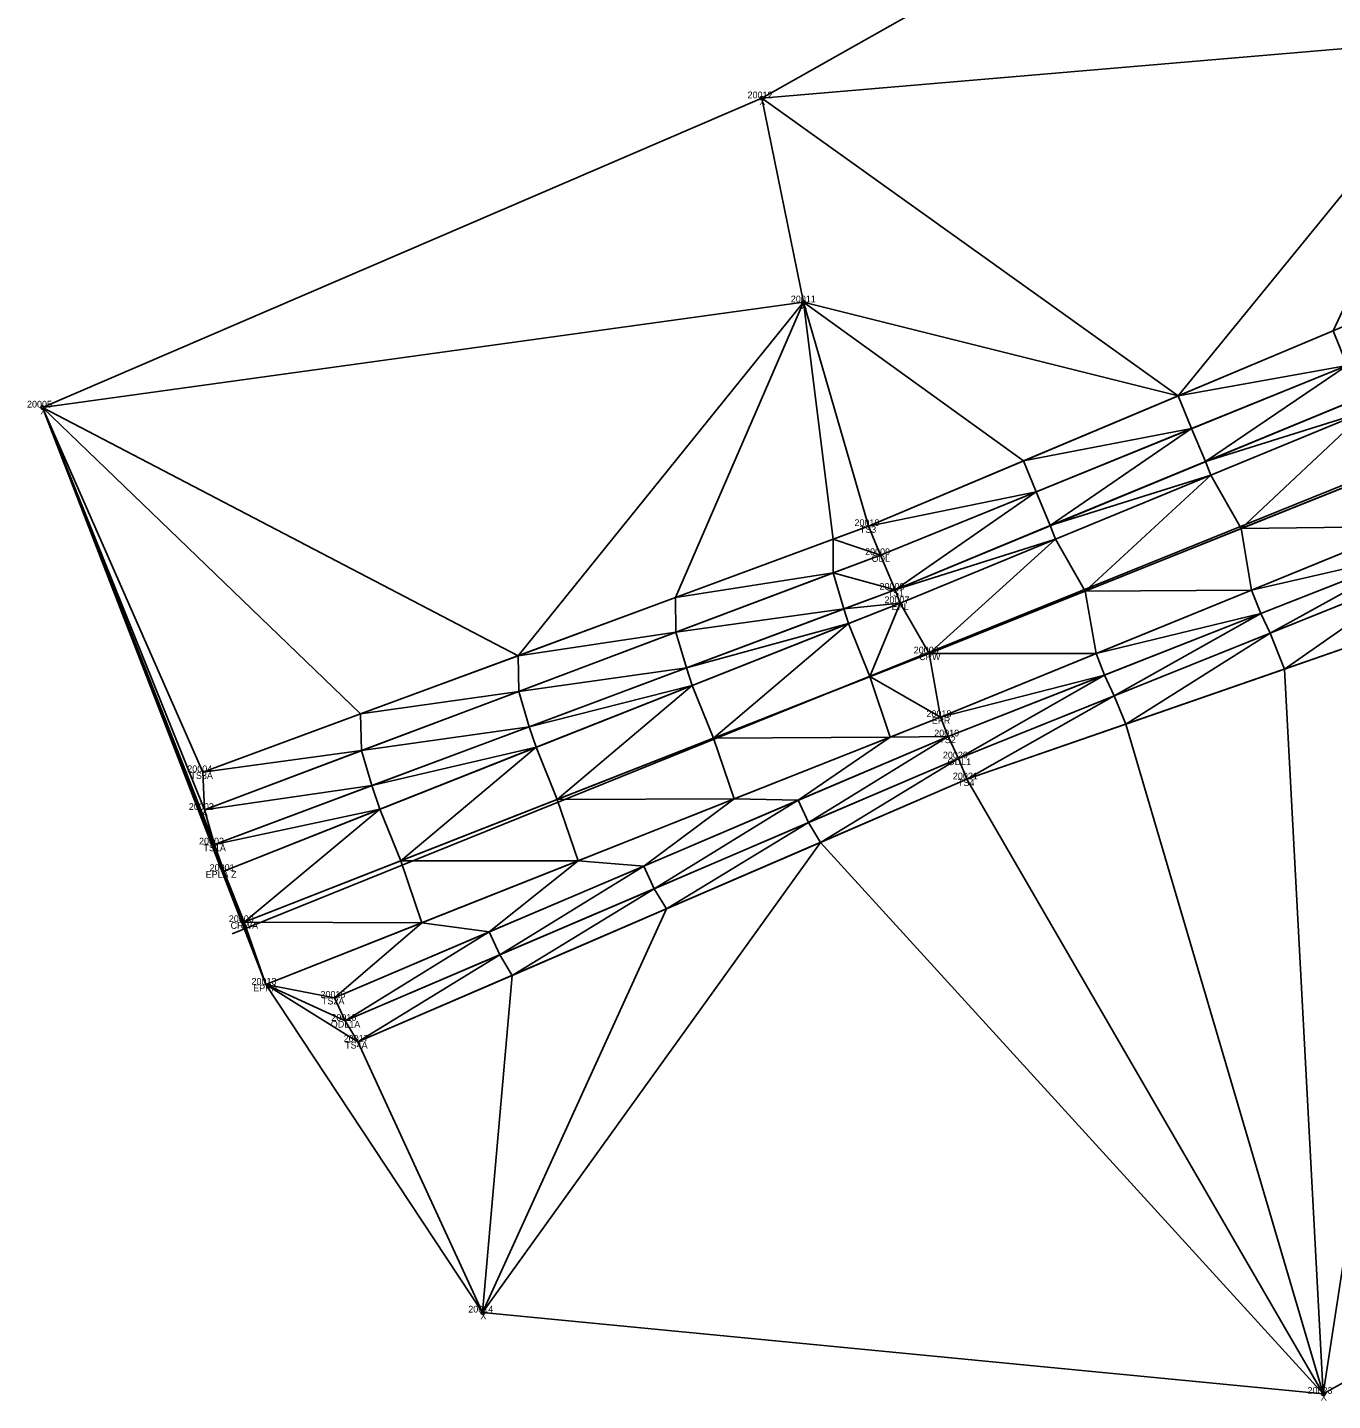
# Model space of a CAD drawing. Extents: x 1966740 to 1969291, y 1117379 to 1118460.
# Drawn here: x 1966740.3 to 1966934.5, y 1117378.7 to 1117583 of the extents above; entities that cross this region are included whole.
import ezdxf

# ---------------------------------------------------------------- set-up
doc = ezdxf.new("R2010")
doc.units = 0
for name, color, linetype in [('Level 1', 7, 'Continuous'), ('Level 3', 7, 'Continuous'), ('Level 30', 7, 'Continuous'), ('Level 35', 7, 'Continuous'), ('Level 50', 7, 'Continuous'), ('Level 52', 7, 'Continuous'), ('Level 53', 7, 'Continuous'), ('Level 56', 7, 'Continuous'), ('Level 6', 7, 'Continuous'), ('Level 62', 7, 'Continuous')]:
    doc.layers.add(name, color=color, linetype=linetype)

msp = doc.modelspace()

# ---------------------------------------------------------------- linework, layer by layer
at = {"layer": 'Level 1'}
msp.add_line((1966770.74, 1117448.12), (1967849.47, 1117883.86), dxfattribs=at)
at = {"layer": 'Level 3'}
for points in [[(1966768.15, 1117461.43), (1966869.41, 1117499.34), (1967070.52, 1117582.35), (1967171.25, 1117624.02), (1967269.74, 1117664.9), (1967320.21, 1117685.71), (1967369.37, 1117708.48), (1967468.51, 1117746.66), (1967564.6, 1117784.47), (1967654.68, 1117828.05), (1967680.1, 1117841.48), (1967687.91, 1117842.93), (1967691.45, 1117838.71), (1967693.03, 1117834.22)], [(1966769.51, 1117457.48), (1966870.16, 1117497.34), (1966971.19, 1117538.95), (1967071.09, 1117580.24), (1967172.6, 1117621.53), (1967270.79, 1117661.66), (1967321.12, 1117682.57), (1967371.52, 1117702.88), (1967470.26, 1117741.55), (1967566.67, 1117779.5), (1967661.25, 1117817.53), (1967694.4, 1117831.19), (1967697.89, 1117822.8)], [(1966772.57, 1117449.88), (1966874.49, 1117489.87), (1966974.64, 1117529.93), (1967075.06, 1117571.68), (1967175.91, 1117613.34), (1967274.11, 1117653.69), (1967325.25, 1117674.8), (1967374.73, 1117695.01), (1967473.9, 1117733.1), (1967569.8, 1117771.9), (1967665.19, 1117809.79), (1967697.89, 1117822.8)], [(1966766.42, 1117472.19), (1966865.47, 1117508.82), (1967066.64, 1117593.45), (1967166.55, 1117636.11), (1967264.62, 1117677.56), (1967315.66, 1117698.57), (1967367.9, 1117716.34), (1967464.92, 1117753.87), (1967560.73, 1117793.63)], [(1966775.75, 1117440.57), (1966876.18, 1117480.39), (1966978.46, 1117522.15), (1967078.26, 1117563.06), (1967180.7, 1117605.06), (1967277.98, 1117644.72), (1967308.82, 1117656.67)], [(1966786.01, 1117438.62), (1966877.32, 1117477.51), (1966981.49, 1117518.47), (1967035.72, 1117540.87), (1967038.77, 1117541.05)], [(1966789.47, 1117432.06), (1966880.12, 1117471.13), (1966985.94, 1117507.88), (1967038.45, 1117537.97), (1967038.77, 1117541.05)]]:
    msp.add_lwpolyline(points, dxfattribs=at)
at = {"layer": 'Level 30'}
for centre in [(1966849.57, 1117572.49), (1966855.79, 1117542.12), (1966742.55, 1117526.46), (1966808.03, 1117391.77), (1966933.11, 1117379.67)]:
    msp.add_circle(centre, 0.25, dxfattribs=at)
at = {"layer": 'Level 35'}
for points in [[(1966849.57, 1117572.49), (1966942.02, 1117624.67), (1966955, 1117581.5)], [(1966849.57, 1117572.49), (1966955, 1117581.5), (1966911.55, 1117528.2)], [(1966911.55, 1117528.2), (1966955, 1117581.5), (1966934.59, 1117537.89)], [(1966742.55, 1117526.46), (1966849.57, 1117572.49), (1966855.79, 1117542.12)], [(1966849.57, 1117572.49), (1966911.55, 1117528.2), (1966855.79, 1117542.12)], [(1966742.55, 1117526.46), (1966855.79, 1117542.12), (1966813.31, 1117489.53)], [(1966813.31, 1117489.53), (1966855.79, 1117542.12), (1966836.76, 1117498.2)], [(1966836.76, 1117498.2), (1966855.79, 1117542.12), (1966860.21, 1117506.87)], [(1966855.79, 1117542.12), (1966911.55, 1117528.2), (1966888.51, 1117518.51)], [(1966855.79, 1117542.12), (1966888.51, 1117518.51), (1966865.47, 1117508.82)], [(1966855.79, 1117542.12), (1966865.47, 1117508.82), (1966860.21, 1117506.87)], [(1966911.55, 1117528.2), (1966934.59, 1117537.89), (1966936.7, 1117532.74)], [(1966911.55, 1117528.2), (1966936.7, 1117532.74), (1966913.55, 1117523.32)], [(1966913.55, 1117523.32), (1966936.7, 1117532.74), (1966915.62, 1117518.41)], [(1966915.62, 1117518.41), (1966936.7, 1117532.74), (1966938.72, 1117527.95)], [(1966742.55, 1117526.46), (1966766.42, 1117472.19), (1966766.64, 1117466.58)], [(1966742.55, 1117526.46), (1966766.64, 1117466.58), (1966768.15, 1117461.43)], [(1966742.55, 1117526.46), (1966768.15, 1117461.43), (1966769.51, 1117457.48)], [(1966742.55, 1117526.46), (1966769.51, 1117457.48), (1966775.75, 1117440.57)], [(1966742.55, 1117526.46), (1966813.31, 1117489.53), (1966789.87, 1117480.86)], [(1966742.55, 1117526.46), (1966789.87, 1117480.86), (1966766.42, 1117472.19)], [(1966888.51, 1117518.51), (1966911.55, 1117528.2), (1966913.55, 1117523.32)], [(1966915.62, 1117518.41), (1966938.72, 1117527.95), (1966939.5, 1117525.9)], [(1966915.62, 1117518.41), (1966939.5, 1117525.9), (1966916.39, 1117516.38)], [(1966916.39, 1117516.38), (1966939.5, 1117525.9), (1966920.9, 1117508.44)], [(1966920.9, 1117508.44), (1966939.5, 1117525.9), (1966944.11, 1117517.72)], [(1966888.51, 1117518.51), (1966913.55, 1117523.32), (1966890.4, 1117513.91)], [(1966890.4, 1117513.91), (1966913.55, 1117523.32), (1966892.51, 1117508.88)], [(1966892.51, 1117508.88), (1966913.55, 1117523.32), (1966915.62, 1117518.41)], [(1966865.47, 1117508.82), (1966888.51, 1117518.51), (1966890.4, 1117513.91)], [(1966892.51, 1117508.88), (1966915.62, 1117518.41), (1966916.39, 1117516.38)], [(1966892.51, 1117508.88), (1966916.39, 1117516.38), (1966893.27, 1117506.86)], [(1966893.27, 1117506.86), (1966916.39, 1117516.38), (1966897.69, 1117499.15)], [(1966897.69, 1117499.15), (1966916.39, 1117516.38), (1966920.9, 1117508.44)], [(1966920.9, 1117508.44), (1966944.11, 1117517.72), (1966945.61, 1117508.74)], [(1966865.47, 1117508.82), (1966890.4, 1117513.91), (1966867.24, 1117504.5)], [(1966867.24, 1117504.5), (1966890.4, 1117513.91), (1966869.41, 1117499.34)], [(1966869.41, 1117499.34), (1966890.4, 1117513.91), (1966892.51, 1117508.88)], [(1966860.21, 1117506.87), (1966865.47, 1117508.82), (1966867.24, 1117504.5)], [(1966869.41, 1117499.34), (1966892.51, 1117508.88), (1966893.27, 1117506.86)], [(1966897.69, 1117499.15), (1966920.9, 1117508.44), (1966922.47, 1117499.29)], [(1966920.9, 1117508.44), (1966945.61, 1117508.74), (1966922.47, 1117499.29)], [(1966922.47, 1117499.29), (1966945.61, 1117508.74), (1966947.1, 1117504.95)], [(1966836.76, 1117498.2), (1966860.21, 1117506.87), (1966860.2, 1117501.85)], [(1966860.2, 1117501.85), (1966860.21, 1117506.87), (1966867.24, 1117504.5)], [(1966869.41, 1117499.34), (1966893.27, 1117506.86), (1966870.16, 1117497.34)], [(1966870.16, 1117497.34), (1966893.27, 1117506.86), (1966874.49, 1117489.87)], [(1966874.49, 1117489.87), (1966893.27, 1117506.86), (1966897.69, 1117499.15)], [(1966860.2, 1117501.85), (1966867.24, 1117504.5), (1966869.41, 1117499.34)], [(1966922.47, 1117499.29), (1966947.1, 1117504.95), (1966923.84, 1117495.8)], [(1966923.84, 1117495.8), (1966947.1, 1117504.95), (1966925.22, 1117492.89)], [(1966925.22, 1117492.89), (1966947.1, 1117504.95), (1966948.42, 1117502.21)], [(1966836.76, 1117498.2), (1966860.2, 1117501.85), (1966836.81, 1117493.03)], [(1966836.81, 1117493.03), (1966860.2, 1117501.85), (1966861.79, 1117496.49)], [(1966860.2, 1117501.85), (1966869.41, 1117499.34), (1966861.79, 1117496.49)], [(1966925.22, 1117492.89), (1966948.42, 1117502.21), (1966927.35, 1117487.53)], [(1966927.35, 1117487.53), (1966948.42, 1117502.21), (1966950.97, 1117495.74)], [(1966813.31, 1117489.53), (1966836.76, 1117498.2), (1966836.81, 1117493.03)], [(1966861.79, 1117496.49), (1966869.41, 1117499.34), (1966870.16, 1117497.34)], [(1966874.49, 1117489.87), (1966897.69, 1117499.15), (1966899.33, 1117489.84)], [(1966897.69, 1117499.15), (1966922.47, 1117499.29), (1966899.33, 1117489.84)], [(1966899.33, 1117489.84), (1966922.47, 1117499.29), (1966923.84, 1117495.8)], [(1966836.81, 1117493.03), (1966861.79, 1117496.49), (1966838.38, 1117487.73)], [(1966838.38, 1117487.73), (1966861.79, 1117496.49), (1966862.48, 1117494.3)], [(1966861.79, 1117496.49), (1966870.16, 1117497.34), (1966862.48, 1117494.3)], [(1966862.48, 1117494.3), (1966870.16, 1117497.34), (1966865.66, 1117486.41)], [(1966865.66, 1117486.41), (1966870.16, 1117497.34), (1966874.49, 1117489.87)], [(1966899.33, 1117489.84), (1966923.84, 1117495.8), (1966900.58, 1117486.65)], [(1966900.58, 1117486.65), (1966923.84, 1117495.8), (1966902.03, 1117483.57)], [(1966902.03, 1117483.57), (1966923.84, 1117495.8), (1966925.22, 1117492.89)], [(1966927.35, 1117487.53), (1966950.97, 1117495.74), (1966933.11, 1117379.67)], [(1966933.11, 1117379.67), (1966950.97, 1117495.74), (1967022.01, 1117429.23)], [(1966838.38, 1117487.73), (1966862.48, 1117494.3), (1966839.24, 1117485.09)], [(1966839.24, 1117485.09), (1966862.48, 1117494.3), (1966842.39, 1117477.27)], [(1966842.39, 1117477.27), (1966862.48, 1117494.3), (1966865.66, 1117486.41)], [(1966813.31, 1117489.53), (1966836.81, 1117493.03), (1966813.42, 1117484.21)], [(1966813.42, 1117484.21), (1966836.81, 1117493.03), (1966838.38, 1117487.73)], [(1966902.03, 1117483.57), (1966925.22, 1117492.89), (1966903.74, 1117479.33)], [(1966903.74, 1117479.33), (1966925.22, 1117492.89), (1966927.35, 1117487.53)], [(1966789.87, 1117480.86), (1966813.31, 1117489.53), (1966813.42, 1117484.21)], [(1966865.66, 1117486.41), (1966874.49, 1117489.87), (1966876.18, 1117480.39)], [(1966874.49, 1117489.87), (1966899.33, 1117489.84), (1966876.18, 1117480.39)], [(1966876.18, 1117480.39), (1966899.33, 1117489.84), (1966900.58, 1117486.65)], [(1966813.42, 1117484.21), (1966838.38, 1117487.73), (1966814.97, 1117478.96)], [(1966814.97, 1117478.96), (1966838.38, 1117487.73), (1966839.24, 1117485.09)], [(1966903.74, 1117479.33), (1966927.35, 1117487.53), (1966933.11, 1117379.67)], [(1966842.39, 1117477.27), (1966865.66, 1117486.41), (1966868.71, 1117477.42)], [(1966865.66, 1117486.41), (1966876.18, 1117480.39), (1966868.71, 1117477.42)], [(1966876.18, 1117480.39), (1966900.58, 1117486.65), (1966877.32, 1117477.51)], [(1966877.32, 1117477.51), (1966900.58, 1117486.65), (1966878.84, 1117474.24)], [(1966878.84, 1117474.24), (1966900.58, 1117486.65), (1966902.03, 1117483.57)], [(1966789.87, 1117480.86), (1966813.42, 1117484.21), (1966790.03, 1117475.4)], [(1966790.03, 1117475.4), (1966813.42, 1117484.21), (1966814.97, 1117478.96)], [(1966814.97, 1117478.96), (1966839.24, 1117485.09), (1966815.99, 1117475.89)], [(1966815.99, 1117475.89), (1966839.24, 1117485.09), (1966819.12, 1117468.14)], [(1966819.12, 1117468.14), (1966839.24, 1117485.09), (1966842.39, 1117477.27)], [(1966878.84, 1117474.24), (1966902.03, 1117483.57), (1966880.12, 1117471.13)], [(1966880.12, 1117471.13), (1966902.03, 1117483.57), (1966903.74, 1117479.33)], [(1966766.42, 1117472.19), (1966789.87, 1117480.86), (1966790.03, 1117475.4)], [(1966868.71, 1117477.42), (1966876.18, 1117480.39), (1966877.32, 1117477.51)], [(1966880.12, 1117471.13), (1966903.74, 1117479.33), (1966933.11, 1117379.67)], [(1966790.03, 1117475.4), (1966814.97, 1117478.96), (1966791.56, 1117470.2)], [(1966791.56, 1117470.2), (1966814.97, 1117478.96), (1966815.99, 1117475.89)], [(1966819.12, 1117468.14), (1966842.39, 1117477.27), (1966845.47, 1117468.21)], [(1966842.39, 1117477.27), (1966868.71, 1117477.42), (1966845.47, 1117468.21)], [(1966845.47, 1117468.21), (1966868.71, 1117477.42), (1966855.01, 1117468.01)], [(1966855.01, 1117468.01), (1966868.71, 1117477.42), (1966877.32, 1117477.51)], [(1966855.01, 1117468.01), (1966877.32, 1117477.51), (1966856.53, 1117464.69)], [(1966856.53, 1117464.69), (1966877.32, 1117477.51), (1966878.84, 1117474.24)], [(1966766.42, 1117472.19), (1966790.03, 1117475.4), (1966766.64, 1117466.58)], [(1966766.64, 1117466.58), (1966790.03, 1117475.4), (1966791.56, 1117470.2)], [(1966791.56, 1117470.2), (1966815.99, 1117475.89), (1966792.75, 1117466.68)], [(1966792.75, 1117466.68), (1966815.99, 1117475.89), (1966795.84, 1117459.01)], [(1966795.84, 1117459.01), (1966815.99, 1117475.89), (1966819.12, 1117468.14)], [(1966856.53, 1117464.69), (1966878.84, 1117474.24), (1966858.34, 1117461.74)], [(1966858.34, 1117461.74), (1966878.84, 1117474.24), (1966880.12, 1117471.13)], [(1966858.34, 1117461.74), (1966880.12, 1117471.13), (1966933.11, 1117379.67)], [(1966766.64, 1117466.58), (1966791.56, 1117470.2), (1966768.15, 1117461.43)], [(1966768.15, 1117461.43), (1966791.56, 1117470.2), (1966792.75, 1117466.68)], [(1966795.84, 1117459.01), (1966819.12, 1117468.14), (1966822.23, 1117459)], [(1966819.12, 1117468.14), (1966845.47, 1117468.21), (1966822.23, 1117459)], [(1966822.23, 1117459), (1966845.47, 1117468.21), (1966832.01, 1117458.21)], [(1966832.01, 1117458.21), (1966845.47, 1117468.21), (1966855.01, 1117468.01)], [(1966832.01, 1117458.21), (1966855.01, 1117468.01), (1966833.56, 1117454.85)], [(1966833.56, 1117454.85), (1966855.01, 1117468.01), (1966856.53, 1117464.69)], [(1966768.15, 1117461.43), (1966792.75, 1117466.68), (1966769.51, 1117457.48)], [(1966769.51, 1117457.48), (1966792.75, 1117466.68), (1966772.57, 1117449.88)], [(1966772.57, 1117449.88), (1966792.75, 1117466.68), (1966795.84, 1117459.01)], [(1966833.56, 1117454.85), (1966856.53, 1117464.69), (1966835.38, 1117451.85)], [(1966835.38, 1117451.85), (1966856.53, 1117464.69), (1966858.34, 1117461.74)], [(1966808.03, 1117391.77), (1966835.38, 1117451.85), (1966858.34, 1117461.74)], [(1966808.03, 1117391.77), (1966858.34, 1117461.74), (1966933.11, 1117379.67)], [(1966772.57, 1117449.88), (1966795.84, 1117459.01), (1966798.99, 1117449.78)], [(1966795.84, 1117459.01), (1966822.23, 1117459), (1966798.99, 1117449.78)], [(1966798.99, 1117449.78), (1966822.23, 1117459), (1966809.01, 1117448.42)], [(1966809.01, 1117448.42), (1966822.23, 1117459), (1966832.01, 1117458.21)], [(1966769.51, 1117457.48), (1966772.57, 1117449.88), (1966775.75, 1117440.57)], [(1966809.01, 1117448.42), (1966832.01, 1117458.21), (1966810.58, 1117445.02)], [(1966810.58, 1117445.02), (1966832.01, 1117458.21), (1966833.56, 1117454.85)], [(1966810.58, 1117445.02), (1966833.56, 1117454.85), (1966812.42, 1117441.95)], [(1966812.42, 1117441.95), (1966833.56, 1117454.85), (1966835.38, 1117451.85)], [(1966808.03, 1117391.77), (1966812.42, 1117441.95), (1966835.38, 1117451.85)], [(1966772.57, 1117449.88), (1966798.99, 1117449.78), (1966775.75, 1117440.57)], [(1966775.75, 1117440.57), (1966798.99, 1117449.78), (1966786.01, 1117438.62)], [(1966786.01, 1117438.62), (1966798.99, 1117449.78), (1966809.01, 1117448.42)], [(1966786.01, 1117438.62), (1966809.01, 1117448.42), (1966787.6, 1117435.18)], [(1966787.6, 1117435.18), (1966809.01, 1117448.42), (1966810.58, 1117445.02)], [(1966787.6, 1117435.18), (1966810.58, 1117445.02), (1966789.47, 1117432.06)], [(1966789.47, 1117432.06), (1966810.58, 1117445.02), (1966812.42, 1117441.95)], [(1966775.75, 1117440.57), (1966786.01, 1117438.62), (1966787.6, 1117435.18)], [(1966775.75, 1117440.57), (1966787.6, 1117435.18), (1966789.47, 1117432.06)], [(1966775.75, 1117440.57), (1966789.47, 1117432.06), (1966808.03, 1117391.77)], [(1966789.47, 1117432.06), (1966812.42, 1117441.95), (1966808.03, 1117391.77)]]:
    msp.add_lwpolyline(points, close=True, dxfattribs=at)
at = {"layer": 'Level 50'}
for centre in [(1966865.47, 1117508.82), (1966867.24, 1117504.5), (1966869.41, 1117499.34), (1966870.16, 1117497.34), (1966874.49, 1117489.87), (1966876.18, 1117480.39), (1966877.32, 1117477.51), (1966878.84, 1117474.24), (1966766.42, 1117472.19), (1966880.12, 1117471.13), (1966766.64, 1117466.58), (1966768.15, 1117461.43), (1966769.51, 1117457.48), (1966772.57, 1117449.88), (1966775.75, 1117440.57), (1966786.01, 1117438.62), (1966787.6, 1117435.18), (1966789.47, 1117432.06)]:
    msp.add_circle(centre, 0.001, dxfattribs=at)
at = {"layer": 'Level 6'}
for points in [[(1966766.64, 1117466.58), (1966867.24, 1117504.5), (1967068.76, 1117586.41), (1967167.95, 1117632.67), (1967266.82, 1117671.88), (1967316.79, 1117693.47), (1967368.01, 1117713.34), (1967465.67, 1117751.74), (1967560.73, 1117793.63)], [(1966787.6, 1117435.18), (1966878.84, 1117474.24), (1966982.42, 1117515.88), (1967036.47, 1117539.68)]]:
    msp.add_lwpolyline(points, dxfattribs=at)

# ---------------------------------------------------------------- texts
at = {"layer": 'Level 52'}
for s, p in [('20012', (1966847.46, 1117572.49)), ('20011', (1966853.9, 1117542.12)), ('20005', (1966740.23, 1117526.46)), ('20014', (1966805.9, 1117391.77)), ('20023', (1966930.79, 1117379.67))]:
    msp.add_text(s, height=1, dxfattribs=at).set_placement(p)
at = {"layer": 'Level 53'}
for s, p in [('20010', (1966863.37, 1117508.82)), ('TS3', (1966864.15, 1117507.82)), ('20008', (1966867.09, 1117499.34)), ('20007', (1966867.84, 1117497.34)), ('TS1', (1966868.3, 1117498.34)), ('EPL', (1966868.9, 1117496.34)), ('20006', (1966872.19, 1117489.87)), ('CRW', (1966872.99, 1117488.87)), ('20018', (1966874.08, 1117480.39)), ('EPR', (1966874.88, 1117479.39)), ('20019', (1966875.24, 1117477.51)), ('TS2', (1966875.99, 1117476.51)), ('20020', (1966876.53, 1117474.24)), ('20004', (1966764.08, 1117472.19)), ('ODL1', (1966877.24, 1117473.24)), ('TS3A', (1966764.55, 1117471.19)), ('20021', (1966878.02, 1117471.13)), ('TS4', (1966878.77, 1117470.13)), ('20002', (1966765.83, 1117461.43)), ('TS1A', (1966766.48, 1117460.43)), ('EPLA Z', (1966766.81, 1117456.48)), ('20001', (1966767.41, 1117457.48)), ('20000', (1966770.26, 1117449.88)), ('CRWA', (1966770.53, 1117448.88)), ('20013', (1966773.64, 1117440.57)), ('EPRA', (1966773.9, 1117439.57)), ('20015', (1966783.9, 1117438.62)), ('TS2A', (1966784.13, 1117437.62)), ('ODL1A', (1966785.44, 1117434.18)), ('20016', (1966785.52, 1117435.18)), ('20017', (1966787.36, 1117432.06)), ('TS4A', (1966787.57, 1117431.06))]:
    msp.add_text(s, height=1, dxfattribs=at).set_placement(p)
at = {"layer": 'Level 56'}
for s, p in [('20009', (1966864.95, 1117504.5)), ('ODL', (1966865.92, 1117503.5)), ('20003', (1966764.32, 1117466.58)), ('A', (1966766.25, 1117465.58))]:
    msp.add_text(s, height=1, dxfattribs=at).set_placement(p)
at = {"layer": 'Level 62'}
for p in [(1966849.23, 1117571.49), (1966855.45, 1117541.12), (1966742.22, 1117525.46), (1966807.7, 1117390.77), (1966932.77, 1117378.67)]:
    msp.add_text('X', height=1, dxfattribs=at).set_placement(p)

doc.saveas('drawing.dxf')
